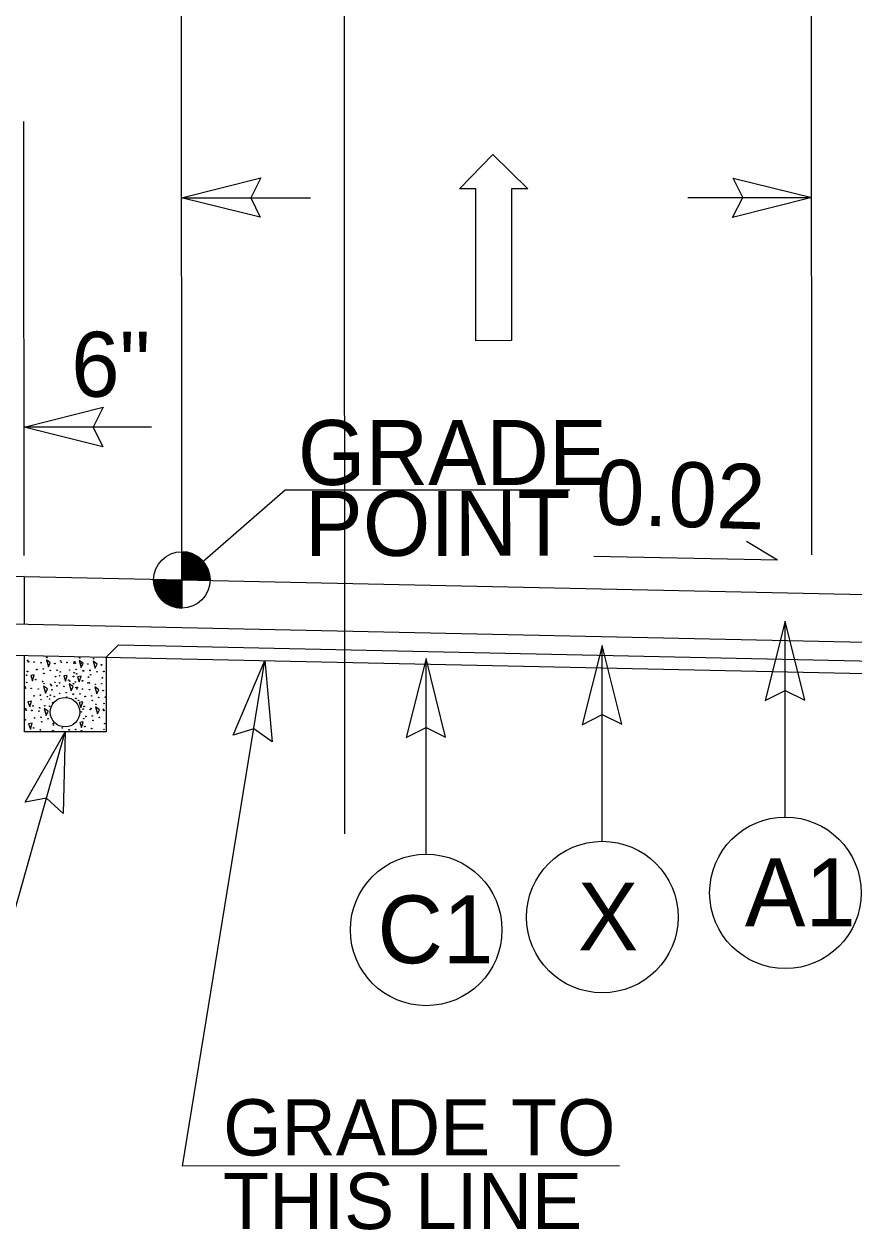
# Model space of a CAD drawing. Extents: x 2241081 to 2251104, y 658534 to 663427.
# Drawn here: x 2244055.6 to 2244161, y 661310.7 to 661463.7 of the extents above; entities that cross this region are included whole.
import ezdxf

# ---------------------------------------------------------------- set-up
doc = ezdxf.new("R2010")
doc.units = 0
for name, color, linetype in [('Old_Level_11', 7, 'Continuous'), ('Old_Level_2', 7, 'Continuous'), ('Old_Level_3', 7, 'Continuous'), ('Prop Dimension Text', 7, 'Continuous'), ('Prop Lane Arrow CELL', 7, 'Continuous'), ('Typical Arrow Superelevation CELL', 7, 'Continuous'), ('Typical Berm Information CELL', 7, 'Continuous'), ('Typical Curb CELL', 7, 'Continuous'), ('Typical Grade Point Symbol CELL', 7, 'Continuous'), ('Typical ID Circle CELL', 7, 'Continuous'), ('Typical Terminator CELL', 7, 'Continuous'), ('Typical Text Centerline CELL', 7, 'Continuous'), ('Typical Text Grade Point CELL', 7, 'Continuous'), ('Typical Text ID Circle CELL', 7, 'Continuous')]:
    doc.layers.add(name, color=color, linetype=linetype)

# ---------------------------------------------------------------- blocks, each defined once
blk = doc.blocks.new('TERMINATOR')
at = {"layer": 'Typical Terminator CELL'}
blk.add_lwpolyline([(-0.4687, 0.0807), (0, 0), (-0.4713, -0.0833), (-0.4114, 0)], close=True, dxfattribs=at)

msp = doc.modelspace()

# ---------------------------------------------------------------- linework, layer by layer
at = {"layer": 'Old_Level_11'}
msp.add_line((2244075.72, 661318.77), (2244086.2, 661382.95), dxfattribs=at)
at = {"layer": 'Old_Level_2'}
for p, q in [((2244055.65, 661393.61), (2244015.65, 661392.31)), ((2244055.65, 661393.61), (2244075.65, 661393.18)), ((2244055.65, 661393.61), (2244055.65, 661387.56)), ((2244075.65, 661393.18), (2244175.65, 661391.04)), ((2244049.3, 661387.7), (2244075.64, 661387.13)), ((2244075.64, 661387.13), (2244181.4, 661384.87)), ((2244067.62, 661384.94), (2244066.06, 661383.38)), ((2244067.62, 661384.94), (2244075.64, 661384.77)), ((2244075.64, 661384.77), (2244163.61, 661382.89)), ((2244045.15, 661383.83), (2244075.64, 661383.18)), ((2244055.65, 661383.61), (2244055.65, 661373.9)), ((2244066.06, 661383.38), (2244066.06, 661373.9)), ((2244075.64, 661383.18), (2244185.16, 661380.83)), ((2244066.06, 661373.9), (2244055.65, 661373.9))]:
    msp.add_line(p, q, dxfattribs=at)
msp.add_circle((2244060.82, 661376.4), 1.87, dxfattribs=at)
at = {"layer": 'Prop Dimension Text'}
for p, q in [((2244075.64, 661396.3), (2244075.59, 661481.89)), ((2244155.64, 661396.35), (2244155.59, 661481.94)), ((2244055.64, 661396.29), (2244055.61, 661451.37)), ((2244075.62, 661441.69), (2244091.99, 661441.7)), ((2244139.88, 661441.73), (2244155.62, 661441.74)), ((2244071.79, 661412.57), (2244055.63, 661412.56)), ((2244048.2, 661329.21), (2244060.85, 661373.9)), ((2244131.21, 661318.8), (2244075.72, 661318.77))]:
    msp.add_line(p, q, dxfattribs=at)
at = {"layer": 'Prop Lane Arrow CELL'}
for p, q in [((2244110.88, 661442.85), (2244115.15, 661447.19)), ((2244115.15, 661447.19), (2244119.56, 661442.85)), ((2244112.95, 661442.85), (2244110.88, 661442.85)), ((2244112.96, 661423.55), (2244112.95, 661442.85)), ((2244119.56, 661442.85), (2244117.5, 661442.85)), ((2244117.5, 661442.85), (2244117.51, 661423.56)), ((2244117.51, 661423.56), (2244112.96, 661423.55))]:
    msp.add_line(p, q, dxfattribs=at)
at = {"layer": 'Typical Arrow Superelevation CELL'}
for q in [(2244147.35, 661398.06), (2244127.96, 661396.16)]:
    msp.add_line((2244151.26, 661395.69), q, dxfattribs=at)
at = {"layer": 'Typical Curb CELL'}
for p, q in [((2244058.46, 661383.02), (2244058.7, 661382.13)), ((2244058.95, 661382.67), (2244058.46, 661383.02)), ((2244058.7, 661382.13), (2244058.95, 661382.67)), ((2244062.63, 661382.97), (2244062.88, 661382.08)), ((2244063.12, 661382.62), (2244062.63, 661382.97)), ((2244064.39, 661382.86), (2244064.64, 661381.97)), ((2244064.88, 661382.51), (2244064.39, 661382.86)), ((2244056.91, 661381.13), (2244056.48, 661381.05)), ((2244056.7, 661380.39), (2244056.91, 661381.13)), ((2244062.88, 661382.08), (2244063.12, 661382.62)), ((2244064.64, 661381.97), (2244064.88, 661382.51)), ((2244056.48, 661381.05), (2244056.7, 661380.39)), ((2244058.09, 661379.69), (2244058.34, 661378.8)), ((2244058.58, 661379.34), (2244058.09, 661379.69)), ((2244061.09, 661381.07), (2244060.65, 661380.99)), ((2244060.65, 661380.99), (2244060.87, 661380.34)), ((2244060.87, 661380.34), (2244061.09, 661381.07)), ((2244061.36, 661380.01), (2244061.61, 661379.12)), ((2244061.85, 661379.66), (2244061.36, 661380.01)), ((2244061.61, 661379.12), (2244061.85, 661379.66)), ((2244062.85, 661380.96), (2244062.41, 661380.88)), ((2244062.41, 661380.88), (2244062.63, 661380.23)), ((2244062.63, 661380.23), (2244062.85, 661380.96)), ((2244064.6, 661379.6), (2244064.85, 661378.71)), ((2244065.09, 661379.25), (2244064.6, 661379.6)), ((2244058.34, 661378.8), (2244058.58, 661379.34)), ((2244064.85, 661378.71), (2244065.09, 661379.25)), ((2244056.55, 661377.79), (2244056.11, 661377.71)), ((2244056.11, 661377.71), (2244056.33, 661377.06)), ((2244056.33, 661377.06), (2244056.55, 661377.79)), ((2244058.18, 661376.88), (2244058.43, 661375.99)), ((2244058.67, 661376.53), (2244058.18, 661376.88)), ((2244058.43, 661375.99), (2244058.67, 661376.53)), ((2244063.06, 661377.71), (2244062.62, 661377.62)), ((2244062.62, 661377.62), (2244062.84, 661376.97)), ((2244062.84, 661376.97), (2244063.06, 661377.71)), ((2244064.69, 661377.06), (2244064.94, 661376.17)), ((2244065.18, 661376.71), (2244064.69, 661377.06)), ((2244064.94, 661376.17), (2244065.18, 661376.71)), ((2244056.63, 661374.99), (2244056.2, 661374.91)), ((2244056.42, 661374.25), (2244056.63, 661374.99)), ((2244063.14, 661375.17), (2244062.71, 661375.08)), ((2244062.71, 661375.08), (2244062.93, 661374.43)), ((2244062.93, 661374.43), (2244063.14, 661375.17)), ((2244056.2, 661374.91), (2244056.42, 661374.25))]:
    msp.add_line(p, q, dxfattribs=at)
for centre in [(2244056.09, 661382.96), (2244056.18, 661382.78), (2244056.89, 661382.75), (2244057.78, 661382.67), (2244058.51, 661383.35), (2244060.26, 661382.9), (2244060.36, 661382.72), (2244061.06, 661382.7), (2244061.95, 661382.62), (2244062.02, 661382.79), (2244062.12, 661382.62), (2244062.69, 661383.29), (2244064.45, 661383.18), (2244055.95, 661381.09), (2244056.05, 661381.56), (2244057.24, 661381.81), (2244058.05, 661381.89), (2244058.13, 661381.32), (2244058.95, 661381.7), (2244059.52, 661382.56), (2244059.81, 661381.72), (2244060.22, 661381.5), (2244061.41, 661381.75), (2244061.98, 661381.4), (2244062.23, 661381.83), (2244062.31, 661381.26), (2244062.82, 661382.59), (2244063.12, 661381.64), (2244063.17, 661381.64), (2244063.69, 661382.51), (2244063.72, 661382.51), (2244063.99, 661381.72), (2244063.99, 661381.67), (2244064.07, 661381.15), (2244064.88, 661381.53), (2244065.45, 661382.4), (2244065.75, 661381.56), (2244055.72, 661379.62), (2244055.95, 661380.17), (2244057.1, 661380.53), (2244057.97, 661380.29), (2244058.15, 661380.01), (2244058.99, 661379.94), (2244059.09, 661379.77), (2244059.54, 661380.18), (2244059.62, 661380.91), (2244059.79, 661379.74), (2244060.13, 661381.03), (2244060.13, 661380.11), (2244060.68, 661379.66), (2244061.28, 661380.47), (2244061.42, 661380.34), (2244061.89, 661380.92), (2244061.89, 661380), (2244062.14, 661380.23), (2244062.23, 661379.53), (2244062.42, 661379.55), (2244063.04, 661380.37), (2244063.72, 661380.12), (2244063.8, 661380.85), (2244063.91, 661380.12), (2244064.66, 661379.93), (2244065.48, 661380.01), (2244065.56, 661380.75), (2244055.82, 661379.45), (2244056.52, 661379.42), (2244056.87, 661378.47), (2244057.42, 661379.34), (2244057.69, 661378.55), (2244058.58, 661378.36), (2244058.86, 661378.07), (2244058.95, 661378.55), (2244059.15, 661379.23), (2244059.45, 661378.39), (2244060.14, 661378.79), (2244060.96, 661378.87), (2244061.04, 661378.3), (2244061.85, 661378.68), (2244062.19, 661378.14), (2244062.33, 661379.36), (2244062.72, 661378.71), (2244063.03, 661379.33), (2244063.38, 661378.38), (2244063.92, 661379.25), (2244064.2, 661378.46), (2244065.09, 661378.27), (2244065.66, 661379.14), (2244065.96, 661378.3), (2244055.81, 661376.82), (2244055.9, 661376.64), (2244056.61, 661376.61), (2244056.74, 661377.2), (2244057.5, 661376.53), (2244057.61, 661376.95), (2244057.77, 661377.98), (2244058.24, 661377.21), (2244058.86, 661377.15), (2244059.26, 661377.58), (2244062.53, 661377.9), (2244063.12, 661376.79), (2244063.25, 661377.11), (2244064.01, 661376.71), (2244064.11, 661376.86), (2244064.28, 661377.89), (2244064.74, 661377.39), (2244065.69, 661376.76), (2244065.75, 661376.6), (2244065.77, 661377.49), (2244055.77, 661375.42), (2244056.96, 661375.67), (2244057.78, 661375.75), (2244057.86, 661375.18), (2244058.67, 661375.56), (2244059.32, 661374.95), (2244062.89, 661376.43), (2244063.19, 661375.58), (2244063.47, 661375.84), (2244064.28, 661375.92), (2244064.36, 661375.35), (2244065.18, 661375.73), (2244065.86, 661374.95), (2244056.83, 661374.39), (2244057.69, 661374.15), (2244059.27, 661374.04), (2244059.32, 661374.03), (2244059.35, 661374.77), (2244060.47, 661374.39), (2244061.34, 661374.15), (2244062.18, 661374.2), (2244062.91, 661374.04), (2244063, 661374.77), (2244063.33, 661374.57), (2244064.2, 661374.32), (2244065.77, 661374.22)]:
    msp.add_circle(centre, 0.0381, dxfattribs=at)
at = {"layer": 'Typical Grade Point Symbol CELL'}
for p, q in [((2244075.65, 661396.76), (2244075.65, 661393.18)), ((2244075.65, 661393.18), (2244075.65, 661396.76)), ((2244072.06, 661393.18), (2244075.65, 661393.18)), ((2244075.65, 661393.18), (2244075.65, 661389.6)), ((2244079.23, 661393.18), (2244075.65, 661393.18))]:
    msp.add_line(p, q, dxfattribs=at)
for points in [[(2244075.7, 661393.18), (2244075.7, 661396.76), (2244075.7, 661396.76)], [(2244075.77, 661393.18), (2244075.77, 661396.76)], [(2244075.84, 661393.18), (2244075.84, 661396.75)], [(2244075.92, 661393.18), (2244075.92, 661396.75)], [(2244075.99, 661393.18), (2244075.99, 661396.74)], [(2244076.06, 661393.18), (2244076.06, 661396.74)], [(2244076.13, 661393.18), (2244076.13, 661396.73)], [(2244076.2, 661393.18), (2244076.2, 661396.71)], [(2244076.27, 661393.18), (2244076.27, 661396.71)], [(2244076.35, 661393.18), (2244076.35, 661396.69)], [(2244076.42, 661393.18), (2244076.42, 661396.67)], [(2244076.49, 661393.18), (2244076.49, 661396.66)], [(2244076.56, 661393.18), (2244076.56, 661396.64)], [(2244076.63, 661393.18), (2244076.63, 661396.62)], [(2244076.7, 661393.18), (2244076.7, 661396.6)], [(2244076.78, 661393.18), (2244076.78, 661396.58)], [(2244076.85, 661393.18), (2244076.85, 661396.55)], [(2244076.92, 661393.18), (2244076.92, 661396.53)], [(2244076.99, 661393.18), (2244076.99, 661396.5)], [(2244077.06, 661393.18), (2244077.06, 661396.47)], [(2244077.13, 661393.18), (2244077.13, 661396.43)], [(2244077.2, 661393.18), (2244077.2, 661396.4)], [(2244077.28, 661393.18), (2244077.28, 661396.37)], [(2244077.35, 661393.18), (2244077.35, 661396.33)], [(2244077.42, 661393.18), (2244077.42, 661396.29)], [(2244077.49, 661393.18), (2244077.49, 661396.25)], [(2244077.56, 661393.18), (2244077.56, 661396.2)], [(2244077.63, 661393.18), (2244077.63, 661396.16)], [(2244077.71, 661393.18), (2244077.71, 661396.11)], [(2244077.78, 661393.18), (2244077.78, 661396.06)], [(2244077.85, 661393.18), (2244077.85, 661396)], [(2244077.92, 661393.18), (2244077.92, 661395.95)], [(2244077.99, 661393.18), (2244077.99, 661395.89)], [(2244078.06, 661393.18), (2244078.06, 661395.82)], [(2244078.14, 661393.18), (2244078.14, 661395.76)], [(2244078.21, 661393.18), (2244078.21, 661395.69)], [(2244078.28, 661393.18), (2244078.28, 661395.61)], [(2244078.35, 661393.18), (2244078.35, 661395.53)], [(2244078.42, 661393.18), (2244078.42, 661395.44)], [(2244078.49, 661393.18), (2244078.49, 661395.35)], [(2244078.57, 661393.18), (2244078.57, 661395.26)], [(2244078.64, 661393.18), (2244078.64, 661395.15)], [(2244078.71, 661393.18), (2244078.71, 661395.04)], [(2244078.78, 661393.18), (2244078.78, 661394.91)], [(2244078.85, 661393.18), (2244078.85, 661394.78)], [(2244078.92, 661393.18), (2244078.92, 661394.63)], [(2244079, 661393.18), (2244079, 661394.46)], [(2244079.07, 661393.18), (2244079.07, 661394.25)], [(2244079.14, 661393.18), (2244079.14, 661393.99)], [(2244079.21, 661393.18), (2244079.21, 661393.57)], [(2244072.1, 661392.67), (2244072.1, 661393.18)], [(2244072.18, 661392.3), (2244072.18, 661393.18)], [(2244072.25, 661392.06), (2244072.25, 661393.18)], [(2244072.32, 661391.86), (2244072.32, 661393.18)], [(2244072.39, 661391.69), (2244072.39, 661393.18)], [(2244072.46, 661391.54), (2244072.46, 661393.18)], [(2244072.53, 661391.41), (2244072.53, 661393.18)], [(2244072.61, 661391.29), (2244072.61, 661393.18)], [(2244072.68, 661391.18), (2244072.68, 661393.18)], [(2244072.75, 661391.08), (2244072.75, 661393.18)], [(2244072.82, 661390.98), (2244072.82, 661393.18)], [(2244072.89, 661390.9), (2244072.89, 661393.18)], [(2244072.96, 661390.81), (2244072.96, 661393.18)], [(2244073.04, 661390.73), (2244073.04, 661393.18)], [(2244073.11, 661390.66), (2244073.11, 661393.18)], [(2244073.18, 661390.59), (2244073.18, 661393.18)], [(2244073.25, 661390.52), (2244073.25, 661393.18)], [(2244073.32, 661390.46), (2244073.32, 661393.18)], [(2244073.39, 661390.4), (2244073.39, 661393.18)], [(2244073.47, 661390.34), (2244073.47, 661393.18)], [(2244073.54, 661390.29), (2244073.54, 661393.18)], [(2244073.61, 661390.24), (2244073.61, 661393.18)], [(2244073.68, 661390.19), (2244073.68, 661393.18)], [(2244073.75, 661390.14), (2244073.75, 661393.18)], [(2244073.82, 661390.1), (2244073.82, 661393.18)], [(2244073.9, 661390.06), (2244073.9, 661393.18)], [(2244073.97, 661390.02), (2244073.97, 661393.18)], [(2244074.04, 661389.98), (2244074.04, 661393.18)], [(2244074.11, 661389.95), (2244074.11, 661393.18)], [(2244074.18, 661389.92), (2244074.18, 661393.18)], [(2244074.25, 661389.89), (2244074.25, 661393.18)], [(2244074.32, 661389.85), (2244074.32, 661393.18)], [(2244074.4, 661389.82), (2244074.4, 661393.18)], [(2244074.47, 661389.8), (2244074.47, 661393.18)], [(2244074.54, 661389.77), (2244074.54, 661393.18)], [(2244074.61, 661389.75), (2244074.61, 661393.18)], [(2244074.68, 661389.73), (2244074.68, 661393.18)], [(2244074.75, 661389.71), (2244074.75, 661393.18)], [(2244074.83, 661389.69), (2244074.83, 661393.18)], [(2244074.9, 661389.68), (2244074.9, 661393.18)], [(2244074.97, 661389.66), (2244074.97, 661393.18)], [(2244075.04, 661389.65), (2244075.04, 661393.18)], [(2244075.11, 661389.64), (2244075.11, 661393.18)], [(2244075.18, 661389.63), (2244075.18, 661393.18)], [(2244075.26, 661389.62), (2244075.26, 661393.18)], [(2244075.33, 661389.62), (2244075.33, 661393.18)], [(2244075.4, 661389.61), (2244075.4, 661393.18)], [(2244075.47, 661389.61), (2244075.47, 661393.18)], [(2244075.54, 661389.6), (2244075.54, 661393.18)], [(2244075.61, 661389.6), (2244075.61, 661389.6), (2244075.61, 661393.18)]]:
    msp.add_lwpolyline(points, dxfattribs=at)
msp.add_circle((2244075.65, 661393.18), 3.58, dxfattribs=at)
for start, end in [(359.9905, 89.9905), (179.9905, 269.9905)]:
    msp.add_arc((2244075.65, 661393.18), 3.58, start, end, dxfattribs=at)
at = {"layer": 'Typical ID Circle CELL'}
for p, q in [((2244152.26, 661363.08), (2244152.26, 661387.93)), ((2244129.03, 661359.99), (2244129.03, 661384.85)), ((2244106.67, 661358.37), (2244106.67, 661383.22))]:
    msp.add_line(p, q, dxfattribs=at)
for centre in [(2244152.27, 661353.46), (2244129.03, 661350.38), (2244106.67, 661348.75)]:
    msp.add_circle(centre, 9.62, dxfattribs=at)
at = {"layer": 'Typical Text Centerline CELL'}
msp.add_line((2244096.35, 661360.95), (2244096.26, 661509.5), dxfattribs=at)
at = {"layer": 'Typical Text Grade Point CELL'}
for p, q in [((2244075.65, 661393.18), (2244088.77, 661404.61)), ((2244088.77, 661404.61), (2244124.89, 661404.64))]:
    msp.add_line(p, q, dxfattribs=at)

# ---------------------------------------------------------------- block references
at = {"layer": 'Typical Terminator CELL'}
for p, xscale, yscale, rotation in [((2244075.62, 661441.69), 21.314641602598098, 30.593161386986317, -179.96511250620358), ((2244155.62, 661441.74), 21.314641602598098, 30.593161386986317, 0.03488749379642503), ((2244055.63, 661412.56), 21.314641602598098, 30.593161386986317, -179.96511250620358), ((2244152.26, 661387.93), 21.3146416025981, -30.593161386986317, 89.9999349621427), ((2244129.03, 661384.85), 21.3146416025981, -30.593161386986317, 89.9999349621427), ((2244086.2, 661382.95), 21.314641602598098, 30.593161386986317, 80.72833125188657), ((2244106.67, 661383.22), 21.3146416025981, -30.593161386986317, 89.9999349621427), ((2244060.85, 661373.9), 21.314641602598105, 30.5931613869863, 74.19108286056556)]:
    msp.add_blockref('TERMINATOR', p, dxfattribs=dict(at, xscale=xscale, yscale=yscale, rotation=rotation))

# ---------------------------------------------------------------- texts
at = {"layer": 'Old_Level_3'}
for s, p in [('GRADE TO', (2244080.89, 661320.12)), ('THIS LINE', (2244080.89, 661310.77))]:
    msp.add_text(s, height=7.131, rotation=359.9999, dxfattribs=at).set_placement(p)
at = {"layer": 'Prop Dimension Text'}
msp.add_text('6"', height=8.25, rotation=0.0349, dxfattribs=at).set_placement((2244061.61, 661416.44))
at = {"layer": 'Typical Berm Information CELL'}
msp.add_text('0.02 ', height=8.25, rotation=358.1916, dxfattribs=at).set_placement((2244128.11, 661400.26))
at = {"layer": 'Typical Text Grade Point CELL'}
for s, p in [('GRADE', (2244090.38, 661405.23)), ('POINT', (2244091.26, 661396.23))]:
    msp.add_text(s, height=8.25, rotation=0.0349, dxfattribs=at).set_placement(p)
at = {"layer": 'Typical Text ID Circle CELL'}
for s, height, p in [('A1', 8.608, (2244147.13, 661349.22)), ('X', 8.61, (2244125.92, 661346.14)), ('C1', 8.608, (2244100.48, 661344.52))]:
    msp.add_text(s, height=height, rotation=359.9999, dxfattribs=at).set_placement(p)

doc.saveas('drawing.dxf')
